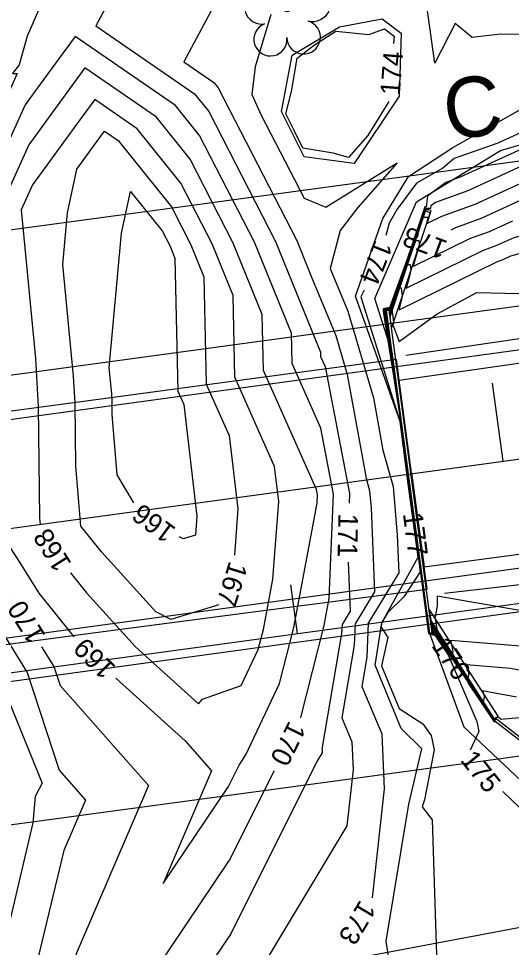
# Model space of a CAD drawing. Extents: x 2086416 to 2115205, y 575507 to 632762.
# Drawn here: x 2112066 to 2112116.2, y 581682.3 to 581776.8 of the extents above; entities that cross this region are included whole.
import ezdxf

# ---------------------------------------------------------------- set-up
doc = ezdxf.new("R2010")
doc.units = 0
for name, color, linetype in [('Default', 7, 'Continuous'), ('DTM Contours Major', 7, 'Continuous'), ('DTM Contours Major Text', 7, 'Continuous'), ('DTM Contours Minor', 7, 'Continuous'), ('DTM Contours Minor Text', 7, 'Continuous'), ('Exist Guardrail', 7, 'Continuous'), ('Exist Hydro Stream or Body of Water', 7, 'Continuous'), ('Exist Hydrographic FEMA Cross Section', 7, 'Continuous'), ('Exist Right of Way Line', 7, 'Continuous'), ('Exist Roads EOP', 7, 'Continuous'), ('Exist Structure Major Bridge WW', 7, 'Continuous'), ('Exist Structure Major Deck Tunnel Box Culvert', 7, 'Continuous'), ('Exist Vegetation Tree CELL', 7, 'Continuous'), ('Prop Horizontal Alignment', 7, 'Continuous'), ('Prop Horizontal Alignment Tick Large', 7, 'Continuous'), ('Prop Roadway Bridge', 7, 'Continuous'), ('Prop SS Cut Line', 7, 'Continuous'), ('Prop SS Cut Text', 7, 'Continuous')]:
    doc.layers.add(name, color=color, linetype=linetype)

# ---------------------------------------------------------------- blocks, each defined once
blk = doc.blocks.new('EXIST VEGETATION TREE')
at = {"layer": 'Exist Vegetation Tree CELL'}
blk.add_line((0, 0), (0, 0), dxfattribs=at)
blk.add_circle((0, 0), 0.00652, dxfattribs=at)
for centre, radius, start, end in [((-0.0077, 0.0575), 0.0371, 330.1651, 219.7134), ((0.051, 0.0118), 0.038, 257.1011, 134.1999), ((-0.0521, 0.0031), 0.0345, 62.6636, 279.3457), ((-0.0341, -0.0624), 0.0338, 111.5671, 6.231), ((0.0335, -0.058), 0.034, 181.2822, 74.56)]:
    blk.add_arc(centre, radius, start, end, dxfattribs=at)

msp = doc.modelspace()

# ---------------------------------------------------------------- linework, layer by layer
at = {"layer": 'Default'}
for p, q in [((2112048.04, 581707.887), (2112618.339, 581785.483)), ((2111430.061, 581649.328), (2112312.029, 581769.688)), ((2111433.036, 581627.53), (2112315.004, 581747.89)), ((2112094.418, 581714.197), (2112093.744, 581719.152))]:
    msp.add_line(p, q, dxfattribs=at)
at = {"layer": 'DTM Contours Major'}
for points in [[(2112093.804, 581744.757), (2112090.042, 581754.014), (2112084.44, 581764.888), (2112082.003, 581767.922), (2112071.785, 581774.964), (2112068.207, 581770.089), (2112066.687, 581768.005), (2112059.39, 581751.908), (2112059.991, 581745.748), (2112060.467, 581736.615), (2112060.524, 581732.474), (2112061.368, 581723.884), (2112065.2, 581717.945)], [(2112107.271, 581718.408), (2112107.011, 581720.415), (2112104.169, 581741.708), (2112103.667, 581744.929), (2112103.375, 581747.122), (2112103.578, 581747.166), (2112103.753, 581747.19), (2112103.841, 581746.714), (2112104.339, 581748.104), (2112105.63, 581751.758), (2112105.895, 581751.758), (2112105.958, 581751.161), (2112105.765, 581750.292), (2112105.481, 581749.341), (2112113.377, 581753.212), (2112114.641, 581753.669), (2112116.475, 581754.51), (2112142.486, 581761.555), (2112144.37, 581761.969), (2112152.892, 581764.375), (2112153.328, 581764.365), (2112159.99, 581765.28), (2112164.963, 581765.862)], [(2112118.062, 581763.867), (2112111.066, 581760.66), (2112109.531, 581760.105), (2112107.648, 581758.718), (2112107.517, 581757.603), (2112107.398, 581757.603), (2112105.963, 581753.367), (2112105.422, 581751.834), (2112103.805, 581747.327), (2112103.798, 581747.367), (2112103.783, 581747.365), (2112103.135, 581747.223), (2112103.165, 581746.997), (2112104.762, 581736.747), (2112105.228, 581733.251), (2112106.028, 581727.069), (2112106.879, 581720.876), (2112107.72, 581714.473), (2112107.763, 581714.187), (2112108.432, 581713.988), (2112108.435, 581713.989), (2112108.433, 581714.005), (2112108.611, 581713.742), (2112109.771, 581712.025), (2112112.702, 581705.241), (2112112.899, 581704.245), (2112111.998, 581702.33)], [(2112094.748, 581705.646), (2112094.754, 581705.658), (2112097.129, 581715.017), (2112097.653, 581717.792), (2112098.093, 581728.382), (2112096.794, 581735.106), (2112093.873, 581741.675), (2112093.804, 581744.757)], [(2112138.399, 581711.597), (2112130.259, 581710.902), (2112122.081, 581710.4), (2112118.952, 581710.106), (2112116.105, 581710.634), (2112111.62, 581711.009), (2112111.602, 581710.95), (2112111.782, 581710.545), (2112111.856, 581710.027), (2112111.763, 581709.651), (2112108.131, 581715.026), (2112108.22, 581714.185), (2112108.051, 581714.162), (2112107.834, 581714.227), (2112107.82, 581714.32), (2112107.547, 581716.398), (2112107.271, 581718.408)], [(2112068.37, 581712.851), (2112069.614, 581710.846), (2112070.244, 581708.913), (2112079.261, 581698.725), (2112071.879, 581681.594), (2112070.022, 581673.879), (2112068.375, 581663.671), (2112075.727, 581668.301), (2112076.939, 581675.447), (2112087.508, 581691.146), (2112092.081, 581700.276)], [(2112115.349, 581698.132), (2112120.526, 581693.141), (2112134.165, 581691.587), (2112156.789, 581693.375), (2112161.111, 581695.134), (2112179.456, 581698.777), (2112193.131, 581703.787), (2112205.816, 581706.664), (2112209.412, 581707.038), (2112211.228, 581707.28)]]:
    msp.add_lwpolyline(points, dxfattribs=at)
at = {"layer": 'DTM Contours Minor'}
for points in [[(2112088.832, 581814.717), (2112079.117, 581800.733), (2112078.139, 581799.131), (2112071.052, 581784.529), (2112066.895, 581774.978), (2112066.081, 581772.081), (2112065.416, 581771.202), (2112065.876, 581771.198), (2112064.244, 581767.513), (2112055.948, 581749.212), (2112056.111, 581747.536), (2112056.41, 581741.807), (2112056.854, 581736.905), (2112057.524, 581734.784), (2112059.14, 581725.01)], [(2112090.867, 581814.656), (2112090.381, 581813.617), (2112080.779, 581799.37), (2112080.326, 581797.56), (2112075.592, 581779.241), (2112073.887, 581776.041), (2112083.954, 581769.103), (2112085.39, 581767.315), (2112092.199, 581754.098), (2112096.773, 581742.846), (2112096.783, 581742.376), (2112097.229, 581741.374), (2112099.723, 581728.458), (2112099.682, 581727.468)], [(2112307.142, 581785.738), (2112301.4, 581785.104), (2112285.905, 581782.951), (2112280.275, 581782.232), (2112257.984, 581779.142), (2112250.535, 581778.186), (2112235.839, 581776.992), (2112231.218, 581776.453), (2112221.989, 581775.375), (2112201.465, 581773.622), (2112194.785, 581772.636), (2112183.064, 581771.258), (2112173.059, 581769.787), (2112153.283, 581767.472), (2112151.503, 581767.081), (2112145.472, 581765.379), (2112134.612, 581762.993), (2112117.11, 581758.253), (2112113.211, 581756.465), (2112110.524, 581755.494), (2112110.041, 581755.257)], [(2112217.816, 581784.761), (2112201.188, 581783.128), (2112192.056, 581780.852), (2112182.632, 581778.883), (2112164.02, 581774.995), (2112153.603, 581773.464), (2112153.187, 581773.415), (2112147.809, 581772.235), (2112147.676, 581772.198), (2112118.865, 581765.87), (2112118.38, 581765.739), (2112114.812, 581764.103), (2112110.366, 581762.541), (2112109.222, 581761.56), (2112106.527, 581760.029), (2112104.587, 581757.383), (2112103.763, 581755.943), (2112103.404, 581754.716)], [(2112087.421, 581780.959), (2112082.853, 581772.387), (2112085.905, 581770.284), (2112086.341, 581769.742), (2112094.357, 581754.182), (2112095.8, 581750.633), (2112098.322, 581744.525), (2112099.495, 581740.557), (2112101.403, 581730.014), (2112101.767, 581728.727), (2112101.91, 581726.997), (2112102.26, 581718.435), (2112100.298, 581715.176), (2112100.199, 581713.005), (2112098.939, 581705.624), (2112099.971, 581703.175), (2112100.091, 581700.325), (2112099.464, 581694.624), (2112089.901, 581678.74)], [(2112139.56, 581778.479), (2112120.846, 581775.075), (2112115.093, 581775.188), (2112112.213, 581774.86), (2112110.474, 581776.28), (2112108.396, 581772.246), (2112107.475, 581779.066)], [(2112091.702, 581777.181), (2112090.119, 581771.853), (2112089.765, 581769.064), (2112090.723, 581766.943), (2112095.114, 581758.513), (2112097.309, 581757.571), (2112104.588, 581762.098), (2112100.566, 581757.534), (2112098.766, 581755.217), (2112097.764, 581751.339), (2112099.559, 581746.993), (2112102.162, 581738.186), (2112103.125, 581732.867), (2112104.174, 581729.167), (2112104.584, 581724.191), (2112104.739, 581720.391), (2112101.636, 581715.237), (2112101.479, 581711.803), (2112100.97, 581708.818), (2112102.999, 581704.002), (2112103.234, 581698.399), (2112102.014, 581687.292)], [(2112094.139, 581765.264), (2112093.237, 581767.084), (2112093.799, 581769.345), (2112094.397, 581772.731), (2112096.147, 581774.115), (2112098.345, 581775.482), (2112101.694, 581775.147), (2112103.279, 581775.728), (2112104.285, 581774.995), (2112104.203, 581774.24)], [(2112090.836, 581746.669), (2112087.884, 581753.931), (2112083.489, 581762.461), (2112080.052, 581766.74), (2112072.781, 581771.751), (2112070.235, 581768.282), (2112067.06, 581763.928), (2112062.833, 581754.603), (2112063.87, 581743.961), (2112064.236, 581736.951), (2112064.376, 581726.748), (2112064.675, 581723.707), (2112066.115, 581721.476), (2112068.073, 581718.32), (2112071.422, 581714.164), (2112071.682, 581713.878)], [(2112087.867, 581748.58), (2112085.726, 581753.847), (2112082.539, 581760.034), (2112078.101, 581765.559), (2112073.777, 581768.539), (2112072.264, 581766.476), (2112067.433, 581759.852), (2112066.276, 581757.299), (2112067.75, 581742.174), (2112068.005, 581737.287), (2112068.16, 581725.983), (2112068.216, 581725.303)], [(2112103.742, 581768.336), (2112101.571, 581764.883), (2112099.629, 581762.644), (2112098.042, 581763.072), (2112094.957, 581763.592), (2112094.139, 581765.264)], [(2112071.003, 581757.024), (2112071.955, 581761.465), (2112074.292, 581764.67), (2112074.774, 581765.326), (2112076.15, 581764.378), (2112081.589, 581757.607), (2112083.569, 581753.763), (2112084.898, 581750.491), (2112085.142, 581739.573), (2112087.471, 581734.336), (2112088.353, 581726.882), (2112087.997, 581722.183)], [(2112117.745, 581761.996), (2112111.781, 581759.262), (2112108.464, 581758.062), (2112108.01, 581757.728), (2112107.978, 581757.459), (2112107.417, 581757.458), (2112106.511, 581754.783), (2112105.205, 581751.088), (2112103.812, 581747.204), (2112103.789, 581747.331), (2112103.742, 581747.325), (2112103.183, 581747.203), (2112103.265, 581746.584), (2112104.643, 581737.739), (2112105.585, 581730.684), (2112106.276, 581725.337), (2112107.012, 581719.98), (2112107.74, 581714.442), (2112107.777, 581714.195), (2112108.355, 581714.023), (2112108.392, 581714.028), (2112108.373, 581714.209), (2112108.433, 581714.12)], [(2112117.427, 581760.124), (2112112.496, 581757.864), (2112109.098, 581756.635), (2112107.635, 581755.918), (2112108.031, 581757.245), (2112107.795, 581757.314), (2112107.436, 581757.313), (2112107.058, 581756.199), (2112104.989, 581750.342), (2112103.82, 581747.082), (2112103.78, 581747.296), (2112103.701, 581747.285), (2112103.231, 581747.183), (2112103.366, 581746.17), (2112104.524, 581738.731), (2112105.941, 581728.117), (2112106.054, 581727.247)], [(2112077.754, 581727.498), (2112076.067, 581730.334), (2112075.563, 581736.481), (2112075.543, 581737.96), (2112075.509, 581738.599), (2112075.253, 581741.23), (2112076.507, 581754.952), (2112077.416, 581759.191)], [(2112077.416, 581759.191), (2112080.638, 581755.179), (2112081.411, 581753.68), (2112081.93, 581752.403), (2112082.232, 581738.873), (2112082.847, 581737.489), (2112084.19, 581726.14), (2112084.044, 581724.22), (2112082.798, 581723.839), (2112082.417, 581724.036)], [(2112086.407, 581717.111), (2112081.544, 581715.624), (2112080.017, 581716.413), (2112074.461, 581722.522), (2112072.362, 581725.127), (2112071.861, 581731.232), (2112071.774, 581737.624), (2112071.63, 581740.386), (2112070.522, 581751.757), (2112071.003, 581757.024)], [(2112107.637, 581756.141), (2112107.71, 581756.385), (2112107.729, 581756.471), (2112107.723, 581756.53), (2112107.221, 581756.528), (2112104.772, 581749.596), (2112103.827, 581746.959), (2112103.771, 581747.261), (2112103.66, 581747.246), (2112103.279, 581747.163), (2112103.466, 581745.757), (2112104.406, 581739.724), (2112106.298, 581725.549), (2112106.774, 581721.873), (2112107.28, 581718.189), (2112107.78, 581714.381), (2112107.806, 581714.211), (2112108.203, 581714.093), (2112108.306, 581714.106), (2112108.252, 581714.618), (2112113.88, 581706.289), (2112114.436, 581705.466), (2112114.833, 581705.74), (2112115.177, 581705.474), (2112121.46, 581706.063)], [(2112107.519, 581716.676), (2112107.368, 581717.848), (2112104.05, 581742.701), (2112103.767, 581744.516), (2112103.423, 581747.102), (2112103.537, 581747.127), (2112103.744, 581747.154), (2112103.848, 581746.592), (2112104.123, 581747.358), (2112104.835, 581749.372), (2112104.98, 581749.373), (2112105.073, 581748.507), (2112104.792, 581747.246), (2112104.763, 581747.149), (2112114.804, 581752.071), (2112115.356, 581752.271), (2112116.157, 581752.638), (2112132.065, 581756.947)], [(2112116.311, 581756.16), (2112113.926, 581755.067), (2112111.951, 581754.353), (2112106.199, 581751.533), (2112106.737, 581753.339), (2112106.844, 581753.816), (2112106.809, 581754.144), (2112106.426, 581754.143), (2112104.556, 581748.85), (2112103.834, 581746.837), (2112103.762, 581747.225), (2112103.619, 581747.206), (2112103.327, 581747.142), (2112103.566, 581745.343), (2112104.287, 581740.716), (2112106.655, 581722.982), (2112107.022, 581720.141), (2112107.413, 581717.293), (2112107.8, 581714.35), (2112107.82, 581714.219), (2112108.127, 581714.128), (2112108.263, 581714.146), (2112108.191, 581714.822), (2112113.35, 581707.188), (2112113.481, 581707.722), (2112113.448, 581707.96), (2112113.249, 581708.405), (2112116.731, 581707.758)], [(2112101.198, 581749.149), (2112100.886, 581748.447), (2112104.67, 581736.355), (2112104.83, 581735.815), (2112104.847, 581735.721), (2112104.915, 581735.479), (2112105.779, 581728.801), (2112106.745, 581721.771), (2112106.914, 581720.488), (2112105.247, 581717.919), (2112103.61, 581716.352), (2112102.974, 581715.297), (2112102.953, 581714.842), (2112103.633, 581713.807), (2112102.967, 581710.92), (2112104.782, 581706.553), (2112107.203, 581705.011), (2112108.052, 581703.821), (2112108.33, 581702.363), (2112107.362, 581697.278), (2112107.128, 581696.554), (2112108.125, 581695.247), (2112108.585, 581681.482)], [(2112107.768, 581714.944), (2112107.724, 581715.281), (2112103.932, 581743.693), (2112103.868, 581744.102), (2112103.471, 581747.082), (2112103.495, 581747.087), (2112103.735, 581747.119), (2112103.855, 581746.469), (2112103.907, 581746.612), (2112104.039, 581746.987), (2112104.066, 581746.987), (2112104.188, 581745.852), (2112104.133, 581745.609), (2112104.765, 581743.902), (2112108.659, 581746.744), (2112112.703, 581748.9), (2112122.622, 581748.662)], [(2112071.312, 581720.365), (2112072.942, 581718.343), (2112077.928, 581712.86), (2112084.354, 581707.032), (2112084.751, 581707.527), (2112088.704, 581708.924), (2112090.437, 581712.579), (2112090.955, 581714.617), (2112091.919, 581719.729), (2112092.517, 581727.623), (2112092.095, 581731.182), (2112088.052, 581740.274), (2112087.867, 581748.58)], [(2112075.936, 581709.656), (2112082.977, 581703.27), (2112085.682, 581700.214), (2112080.753, 581688.777), (2112087.394, 581698.641), (2112088.478, 581700.806), (2112089.152, 581701.856), (2112092.596, 581709.118), (2112094.042, 581714.817), (2112096.427, 581727.468), (2112096.462, 581728.307), (2112096.359, 581728.839), (2112090.963, 581740.975), (2112090.836, 581746.669)], [(2112111.792, 581709.149), (2112114.444, 581705.224), (2112114.542, 581705.292), (2112119.327, 581701.586), (2112120.838, 581701.727), (2112148.974, 581703.457), (2112150.668, 581703.601), (2112159.721, 581704.147), (2112160.026, 581704.174), (2112185.809, 581706.879), (2112189.823, 581707.604), (2112196.012, 581707.9), (2112209.237, 581709.275), (2112223.325, 581711.149), (2112238.713, 581713.223), (2112245.11, 581713.27), (2112258.687, 581714.946), (2112279.049, 581720.19), (2112287.683, 581722.509), (2112302.257, 581726.24), (2112306.106, 581727.279)], [(2112099.576, 581721.473), (2112099.78, 581716.479), (2112098.959, 581715.116), (2112098.918, 581714.208), (2112096.908, 581702.431), (2112096.943, 581702.348), (2112096.947, 581702.252), (2112096.926, 581702.059), (2112096.427, 581701.231), (2112087.623, 581683.652), (2112083.11, 581676.95), (2112080.122, 581659.325), (2112072.602, 581654.589), (2112064.961, 581649.817), (2112068.331, 581640.74)], [(2112106.842, 581721.299), (2112107.146, 581719.085), (2112107.76, 581714.411), (2112107.792, 581714.203), (2112108.279, 581714.058), (2112108.349, 581714.067), (2112108.312, 581714.413), (2112112.124, 581708.773), (2112114.44, 581705.345), (2112114.687, 581705.516), (2112117.252, 581703.53), (2112121.149, 581703.895), (2112144.296, 581705.318), (2112151.059, 581705.895), (2112158.25, 581706.329), (2112159.831, 581706.466), (2112180.117, 581708.595), (2112189.579, 581710.304), (2112204.165, 581711.003), (2112209.062, 581711.512)], [(2112061.214, 581719.459), (2112062.599, 581717.028), (2112064.756, 581713.686), (2112066.895, 581710.238), (2112070.142, 581700.284), (2112072.84, 581697.236), (2112070.631, 581692.11), (2112066.05, 581673.082), (2112062.824, 581653.079), (2112059.859, 581649.8), (2112053.487, 581643.439), (2112049.372, 581635.991)], [(2112121.699, 581717.534), (2112116.85, 581716.592), (2112108.635, 581718.001), (2112108.639, 581717.019), (2112108.444, 581715.847), (2112108.423, 581715.779), (2112108.452, 581715.715), (2112108.605, 581714.636), (2112108.59, 581714.576), (2112108.01, 581715.434), (2112108.133, 581714.263), (2112107.899, 581714.232), (2112107.862, 581714.243), (2112107.86, 581714.258), (2112107.814, 581714.607), (2112107.768, 581714.944)], [(2112120.062, 581712.659), (2112110.053, 581713.496), (2112110.012, 581713.365), (2112110.117, 581713.13), (2112110.23, 581712.332), (2112110.177, 581712.114), (2112108.07, 581715.23), (2112108.176, 581714.224), (2112107.975, 581714.197), (2112107.848, 581714.235), (2112107.84, 581714.289), (2112107.68, 581715.502), (2112107.519, 581716.676)], [(2112064.52, 581708.577), (2112068.431, 581698.956), (2112067.724, 581697.623), (2112067.493, 581694.94), (2112064.508, 581682.376)]]:
    msp.add_lwpolyline(points, dxfattribs=at)
at = {"layer": 'Exist Guardrail'}
for points in [[(2112105.471, 581742.51), (2112130.199, 581746.155), (2112154.81, 581750.731), (2112204.013, 581759.862), (2112253.579, 581766.728), (2112303.016, 581773.358), (2112346.602, 581779.364), (2112403.93, 581787.617)], [(2112259.946, 581734.593), (2112208.584, 581729.222), (2112158.945, 581723.773), (2112134.486, 581721.17), (2112109.385, 581718.283)]]:
    msp.add_lwpolyline(points, dxfattribs=at)
at = {"layer": 'Exist Hydro Stream or Body of Water'}
for points in [[(2112100.331, 581748.533), (2112103.118, 581756.422), (2112105.733, 581760.694), (2112110.228, 581763.659), (2112118.219, 581768.137), (2112152.909, 581774.525), (2112200.706, 581786.301), (2112247.28, 581789.733), (2112301.109, 581801.74), (2112342.553, 581803.718), (2112346.945, 581801.461), (2112350.791, 581799.078), (2112399.711, 581802.75), (2112440.348, 581810.488), (2112440.68, 581811.969), (2112437.892, 581820.198), (2112440.302, 581822.201), (2112435.858, 581828.249), (2112435.37, 581831.558), (2112437.975, 581841.005), (2112494.538, 581874.355), (2112499.44, 581880.388)], [(2112098.7, 581775.942), (2112103.054, 581776.74), (2112104.994, 581775.3), (2112104.794, 581768.879), (2112100.185, 581762.019), (2112095.093, 581762.7), (2112092.786, 581767.324), (2112093.896, 581773.036), (2112098.7, 581775.942)], [(2112103.025, 581715.299), (2112106.718, 581721.952), (2112105.687, 581729.444), (2112104.878, 581735.772), (2112100.331, 581748.533)], [(2112104.687, 581741.031), (2112104.691, 581741.072)], [(2112107.467, 581653.639), (2112110.029, 581662.341), (2112109.602, 581672.435), (2112103.868, 581680.243), (2112103.47, 581682.891), (2112105.771, 581696.844), (2112107.086, 581702.477), (2112104.983, 581704.544), (2112102.349, 581710.986), (2112103.025, 581715.299)]]:
    msp.add_lwpolyline(points, dxfattribs=at)
at = {"layer": 'Exist Hydrographic FEMA Cross Section'}
msp.add_lwpolyline([(2112356.495, 581719.738), (2112346.578, 581718.488), (2112341.62, 581717.863), (2112336.656, 581717.238), (2112326.74, 581715.988), (2112316.823, 581714.732), (2112306.906, 581713.482), (2112296.99, 581712.232), (2112287.073, 581710.977), (2112277.156, 581709.727), (2112267.239, 581708.477), (2112257.323, 581707.222), (2112247.406, 581705.972), (2112237.489, 581704.722), (2112227.573, 581703.467), (2112217.656, 581702.217), (2112207.74, 581700.967), (2112201.875, 581700.225), (2111922.666, 581647.707)], dxfattribs=at)
at = {"layer": 'Exist Right of Way Line'}
for radius in [86637.248, 86697.248]:
    msp.add_arc((2100483.795, 667614.96), radius, 277.64238767, 277.77100557, dxfattribs=at)
at = {"layer": 'Exist Roads EOP'}
for points in [[(2112106.042, 581730.564), (2112104.785, 581739.983), (2112155.283, 581747.155), (2112204.047, 581753.613), (2112253.47, 581760.299), (2112302.941, 581766.962), (2112352.114, 581773.791), (2112401.717, 581780.294), (2112450.223, 581786.9), (2112499.859, 581793.893), (2112548.734, 581800.819), (2112597.587, 581807.574), (2112647.293, 581814.654)], [(2112106.042, 581730.564), (2112107.323, 581720.971), (2112157.697, 581727.695), (2112206.747, 581734.204), (2112256.301, 581741.075), (2112305.324, 581747.934), (2112354.53, 581754.867), (2112403.988, 581761.609), (2112453.008, 581768.182), (2112502.287, 581774.875), (2112551.211, 581782.051), (2112600.406, 581788.813), (2112649.895, 581795.881)]]:
    msp.add_lwpolyline(points, dxfattribs=at)
at = {"layer": 'Exist Structure Major Bridge WW'}
for points in [[(2112104.008, 581745.313), (2112103.857, 581746.441), (2112107.449, 581757.21), (2112107.923, 581757.052), (2112104.008, 581745.313)], [(2112103.484, 581747.076), (2112103.732, 581747.109), (2112108.116, 581714.279), (2112107.868, 581714.246), (2112103.484, 581747.076)], [(2112107.832, 581716.677), (2112107.987, 581715.512), (2112114.435, 581705.504), (2112114.855, 581705.775), (2112107.832, 581716.677)]]:
    msp.add_lwpolyline(points, dxfattribs=at)
at = {"layer": 'Exist Structure Major Deck Tunnel Box Culvert'}
msp.add_lwpolyline([(2112052.266, 581735.09), (2112052.556, 581733.019), (2112053.866, 581723.651), (2112055.279, 581713.547), (2112055.513, 581711.876), (2112073.348, 581714.22), (2112090.179, 581716.432), (2112107.623, 581718.725), (2112107.323, 581720.971), (2112106.042, 581730.564), (2112104.785, 581739.983), (2112104.506, 581742.07), (2112086.984, 581739.728), (2112070.121, 581737.475), (2112052.266, 581735.09)], dxfattribs=at)
at = {"layer": 'Prop Horizontal Alignment'}
msp.add_line((2111431.548, 581638.429), (2112404.465, 581771.2), dxfattribs=at)
at = {"layer": 'Prop Horizontal Alignment Tick Large'}
msp.add_line((2112115.353, 581731.746), (2112114.271, 581739.672), dxfattribs=at)
at = {"layer": 'Prop Roadway Bridge'}
for p, q in [((2112118.223, 581747.697), (2112038.957, 581736.88)), ((2112043.126, 581706.33), (2112122.392, 581717.147))]:
    msp.add_line(p, q, dxfattribs=at)
at = {"layer": 'Prop SS Cut Line'}
for p, q in [((2112115.106, 581763.341), (2112117.304, 581763.989)), ((2112106.542, 581758.12), (2112115.106, 581763.341)), ((2112102.317, 581748.288), (2112106.542, 581758.12)), ((2112104.047, 581742.86), (2112102.317, 581748.288)), ((2112104.047, 581742.86), (2112107.868, 581714.246)), ((2112107.868, 581714.246), (2112111.36, 581704.719)), ((2112111.36, 581704.719), (2112119.344, 581697.161))]:
    msp.add_line(p, q, dxfattribs=at)

# ---------------------------------------------------------------- block references
at = {"layer": 'Exist Vegetation Tree CELL', "xscale": 50, "yscale": 50}
msp.add_blockref('EXIST VEGETATION TREE', (2112093.376, 581777.779), dxfattribs=at)

# ---------------------------------------------------------------- texts
at = {"layer": 'DTM Contours Major Text'}
for s, rotation, p in [('170', 121.88866, (2112068.839, 581713.996)), ('170', 243.58679, (2112093.58, 581705.418)), ('175', 308.59335, (2112110.926, 581701.299))]:
    msp.add_text(s, height=2, rotation=rotation, dxfattribs=at).set_placement(p)
at = {"layer": 'DTM Contours Minor Text'}
for s, rotation, p in [('174', 85.5338, (2112104.838, 581768.904)), ('178', 159.80411, (2112109.828, 581754.09)), ('174', 248.38648, (2112102.326, 581754.374)), ('166', 143.40898, (2112082.162, 581724.868)), ('171', 268.98519, (2112098.592, 581726.425)), ('177', 277.54556, (2112105.149, 581726.396)), ('168', 122.08741, (2112071.477, 581721.317)), ('167', 252.59032, (2112087.493, 581721.648)), ('169', 135.21165, (2112076.022, 581710.789)), ('176', 304.04957, (2112108.01, 581712.96)), ('173', 239.36469, (2112100.808, 581687.175))]:
    msp.add_text(s, height=2, rotation=rotation, dxfattribs=at).set_placement(p)
at = {"layer": 'Prop SS Cut Text'}
msp.add_text('C', height=6.104, rotation=7.77101, dxfattribs=at).set_placement((2112109.713, 581764.366))

doc.saveas('drawing.dxf')
